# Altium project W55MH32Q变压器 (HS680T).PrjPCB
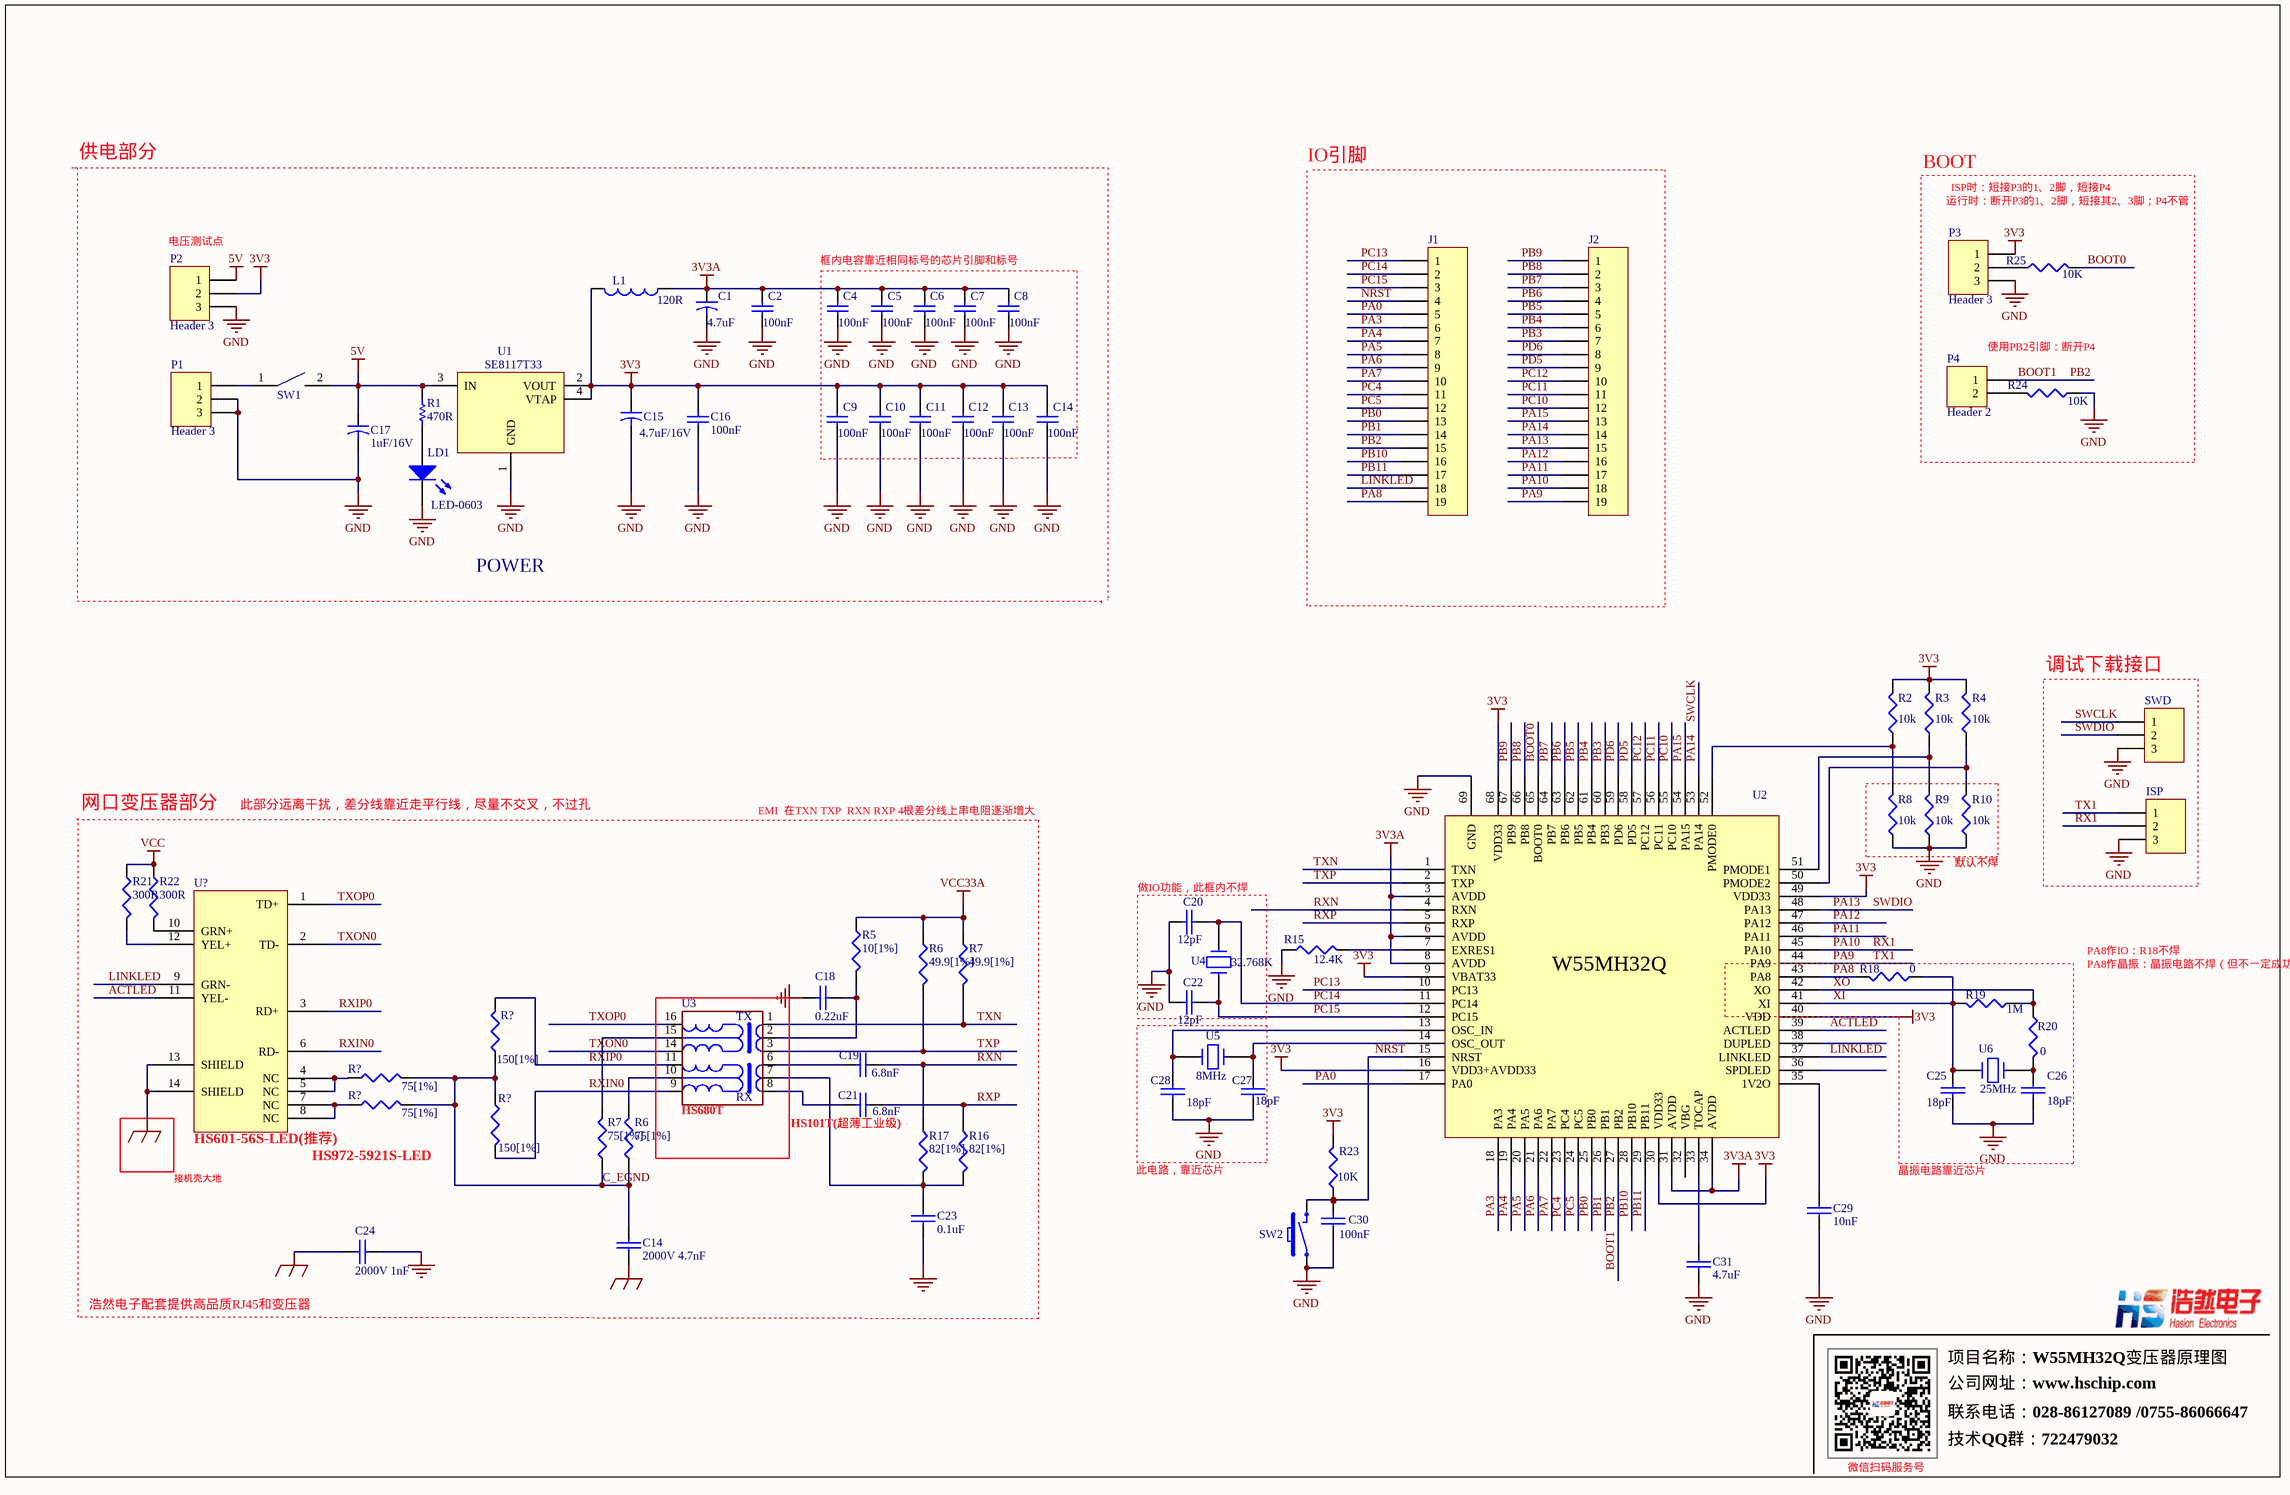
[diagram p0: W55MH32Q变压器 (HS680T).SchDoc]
1 sheet, 77 parts. Net scope: global (net labels, ports and power ports of the same name join across sheets).

## Sheet W55MH32Q变压器 (HS680T).SchDoc
size 431 x 279 mm; PageSetup: Record=PageOptions?CenterHorizontal=True?CenterVertical=True?PrintScale=0.68?XCorrection=1.00?YCorrection=1.00?PrintKind=0?BorderSize=5000000?LeftOffset=0?BottomOffset=0?Orientation=2?PaperLength=1000?PaperWidth=1000?Scale=100?PaperSource=7?PrintQuality=-4?MediaType=1?DitherType=10?PaperKind=A4?PrintScaleMode=1

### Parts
(Parts that share a designator on the sheet are numbered #1, #2 ... from top to bottom, then left to right.)
C1  4.7uF  [3216]
C2  100nF  [0402]
C4  100nF  [0402]
C5  100nF  [0402]
C6  100nF  [0402]
C7  100nF  [0402]
C8  100nF  [0402]
C9  100nF  [0402]
C10  100nF  [0402]
C11  100nF  [0402]
C12  100nF  [0402]
C13  100nF  [0402]
C14#1  100nF  [0402]
C14#2  2000V 4.7nF  [0603]
C15  4.7uF/16V  [3216]
C16  100nF  [0402]
C17  1uF/16V  [3216]
C18  0.22uF  [0603]
C19  6.8nF  [0603]
C20  12pF  [0402]
C21  6.8nF  [0603]
C22  12pF  [0402]
C23  0.1uF  [0603]
C24  2000V 1nF  [0603]
C25  18pF  [0402]
C26  18pF  [0402]
C27  18pF  [0402]
C28  18pF  [0402]
C29  10nF  [0402]
C30  100nF  [0402]
C31  4.7uF  [3216]
ISP  Header 3  [HDR1X3]  (value not drawn)
J1  Header 19  [SIP19]  (value not drawn)
J2  Header 19  [SIP19]  (value not drawn)
L1  120R  [0603]
LD1  LED-0603  [0603 - LED]
P1  Header 3  [PLUG]
P2  Header 3  [HDR1X3]
P3  Header 3  [HDR1X3]
P4  Header 2  [HDR1X2]
R1  470R  [0402]
R2  10k  [0402]
R3  10k  [0402]
R4  10k  [0402]
R5  10[1%]  [0603]
R6#1  49.9[1%]  [0603]
R6#2  75[1%]  [0603]
R7#1  49.9[1%]  [0603]
R7#2  75[1%]  [0603]
R8  10k  [0402]
R9  10k  [0402]
R10  10k  [0402]
R15  12.4K  [0402]
R16  82[1%]  [0603]
R17  82[1%]  [0603]
R18  0  [0402]
R19  1M  [0402]
R20  0  [0402]
R21  300R  [0603]
R22  300R  [0603]
R23  10K  [0402]
R24  10K  [0402]
R25  10K  [0402]
R?#1  150[1%]  [0603]
R?#2  75[1%]  [0603]
R?#3  75[1%]  [0603]
R?#4  150[1%]  [0603]
SW1  SW  [SWITCH-3]  (value not drawn)
SW2  RSTn  [PB-4]  (value not drawn)
SWD  Header 3  [HDR1X3]  (value not drawn)
U1  SE8117T33  [SOT-223]
U2  W55MH32Q  [QFN68-W55MH32Q 8X8-P0.4-EP5.5]  (value not drawn)
U3  HS680T  [TR-HS101T/HS102T/HS680T]
U4  32.768K  [OSC-CH206-RA - 2]
U5  8MHz  [XTAL-49S]
U6  25MHz  [XTAL-49S]
U?  HS601-56S-LED(推荐)  [RJ45-HS601-56S-LED]

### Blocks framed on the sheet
BOOT: P3 P4 R24 R25
框内电容靠近相同标号的芯片引脚和标号: C4-C13 C14#1
调试下载接口: ISP SWD
网口变压器部分: C14#2 C18 C19 C21 C23 C24 R5 R6#1 R6#2 R7#1 R7#2 R16 R17 R21 R22 R?#1-R?#4 U3 U?
做IO功能，此框内不焊: C20 C22 U4

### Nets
3V3: C9.2 C10.2 C11.2 C12.2 C13.2 C14#1.2 C15.1 C16.2 L1.2 P2.2 P3.1 R2.2 R3.2 R4.2 R23.2 U1.2(VOUT) U1.4(VTAP) U2.9(VBAT33) U2.16(VDD3+AVDD33) U2.30(VDD33) U2.40(VDD) U2.49(VDD33) U2.68(VDD33)
3V3A: C1.1 C2.2 C4.2 C5.2 C6.2 C7.2 C8.2 L1.1 U2.3(AVDD) U2.6(AVDD) U2.8(AVDD) U2.31(AVDD) U2.34(AVDD)
5V: C17.1 P2.1 R1.1 SW1.2 U1.3(IN)
EARTH: C14#2.1 C24.1 U?.13(SHIELD) U?.14(SHIELD)
GND: C1.2 C2.1 C4.1 C5.1 C6.1 C7.1 C8.1 C9.1 C10.1 C11.1 C12.1 C13.1 C14#1.1 C15.2 C16.1 C17.2 C18.1 C20.1 C22.1 C23.1 C24.2 C25.2 C26.2 C27.2 C28.2 C29.2 C30.1 C31.2 ISP.3 LD1.2(K) P1.2 P1.3 P2.3 P3.3 R8.1 R9.1 R10.1 R15.1 R24.1 SW2.1 SWD.3 U1.1(GND) U2.69(GND)
VCC: R21.2 R22.2
VCC33A: R5.2 R6#1.2 R7#1.2
ACTLED: U2.39(ACTLED) U?.11(YEL-)
BOOT0: R25.1 U2.65(BOOT0)
BOOT1: J1.15 P4.1 U2.27(PB2)  [also labelled PB2]
C_EGND: C14#2.2 R6#2.2 R7#2.2 R?#1.2 R?#2.1 R?#3.1 R?#4.2
LINKLED: J1.18 U2.37(LINKLED) U?.9(GRN-)
NRST: C30.2 J1.4 R23.1 SW2.2 U2.15(NRST)
PA0: J1.5 U2.17(PA0)
PA3: J1.6 U2.18(PA3)
PA4: J1.7 U2.19(PA4)
PA5: J1.8 U2.20(PA5)
PA6: J1.9 U2.21(PA6)
PA7: J1.10 U2.22(PA7)
PA8: J1.19 R18.2 U2.43(PA8)
PA9: ISP.1 J2.19 U2.44(PA9)  [also labelled TX1]
PA10: ISP.2 J2.18 U2.45(PA10)  [also labelled RX1]
PA11: J2.17 U2.46(PA11)
PA12: J2.16 U2.47(PA12)
PA13: J2.15 SWD.2 U2.48(PA13)  [also labelled SWDIO]
PA14: J2.14 SWD.1 U2.53(PA14)  [also labelled SWCLK]
PA15: J2.13 U2.54(PA15)
PB0: J1.13 U2.25(PB0)
PB1: J1.14 U2.26(PB1)
PB3: J2.7 U2.60(PB3)
PB4: J2.6 U2.61(PB4)
PB5: J2.5 U2.62(PB5)
PB6: J2.4 U2.63(PB6)
PB7: J2.3 U2.64(PB7)
PB8: J2.2 U2.66(PB8)
PB9: J2.1 U2.67(PB9)
PB10: J1.16 U2.28(PB10)
PB11: J1.17 U2.29(PB11)
PC4: J1.11 U2.23(PC4)
PC5: J1.12 U2.24(PC5)
PC10: J2.12 U2.55(PC10)
PC11: J2.11 U2.56(PC11)
PC12: J2.10 U2.57(PC12)
PC13: J1.1 U2.10(PC13)
PC14: C20.2 J1.2 U2.11(PC14) U4.1
PC15: C22.2 J1.3 U2.12(PC15) U4.2
PD5: J2.9 U2.58(PD5)
PD6: J2.8 U2.59(PD6)
RXIN0: R?#4.1 U3.9 U?.6(RD-)
RXIP0: R?#1.1 U3.11 U?.3(RD+)
RXN: C19.1 R17.2 U2.4(RXN)
RXP: C21.1 R16.2 U2.5(RXP)
TXN: R7#1.1 U2.1(TXN) U3.1
TXON0: U3.14 U?.2(TD-)
TXOP0: U3.16 U?.1(TD+)
TXP: R6#1.1 U2.2(TXP) U3.3
XI: C25.1 R18.1 R19.2 U2.41(XI) U6.1
XO: R19.1 R20.1 U2.42(XO)
NetC18_2: C18.2 R5.1 U3.2
NetC19_2: C19.2 U3.6
NetC21_2: C21.2 U3.8
NetC23_2: C23.2 R16.1 R17.1 U3.7
NetC26_1: C26.1 R20.2 U6.2
NetC27_1: C27.1 U2.14(OSC_OUT) U5.1
NetC28_1: C28.1 U2.13(OSC_IN) U5.2
NetC29_1: C29.1 U2.35(1V2O)
NetC31_1: C31.1 U2.33(TOCAP)
NetLD1_1: LD1.1(A) R1.2
NetP1_1: P1.1 SW1.1
NetP3_2: P3.2 R25.2
NetP4_2: P4.2 R24.2
NetR2_1: R2.1 R8.2 U2.52(PMODE0)
NetR3_1: R3.1 R9.2 U2.51(PMODE1)
NetR4_1: R4.1 R10.2 U2.50(PMODE2)
NetR6#2_1: R6#2.1 U3.10
NetR7#2_1: R7#2.1 U3.15
NetR15_2: R15.2 U2.7(EXRES1)
NetR21_1: R21.1 U?.12(YEL+)
NetR22_1: R22.1 U?.10(GRN+)
NetR?#2_2: R?#2.2 U?.4(NC) U?.5(NC)
NetR?#3_2: R?#3.2 U?.7(NC) U?.8(NC)

Not connected (* = marked no-connect by the designer): U2 32(VBG) 36(SPDLED) 38(DUPLED)

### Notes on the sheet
- 供电部分
- IO引脚
- 运行时：断开P3的1、2脚，短接其2、3脚；P4不管
- ISP时：短接P3的1、2脚，短接P4
- (near P2) 电压测试点
- 使用PB2引脚：断开P4
- POWER
- 此部分远离干扰，差分线靠近走平行线，尽量不交叉，不过孔
- EMI  在TXN TXP  RXN RXP 4根差分线上串电阻逐渐增大
- 默认不焊
- PA8作晶振：晶振电路不焊（但不一定成功）
- PA8作IO：R18不焊
- (near U?) HS972-5921S-LED
- (near U3) HS101T(超薄工业级)
- 接机壳大地
- 此电路，靠近芯片
- 晶振电路靠近芯片
- 浩然电子配套提供高品质RJ45和变压器
- 项目名称：W55MH32Q变压器原理图
- 公司网址：www.hschip.com
- 联系电话：028-86127089 /0755-86066647
- 微信扫码服务号
- 技术QQ群：722479032

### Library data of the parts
C1 C15 C17 = CAP-A Size: Tantla CAP A Size EIA/IECQ 3216
C2 C4-C13 C14#1 C16 = CAP-0603: Ceramic CAP 0603(1608)
C14#2 C18-C31 = CAP: Capacitor
ISP P1-P3 SWD = Header 3: Header, 3-Pin
J1 J2 = Header 19: Header, 18-Pin
L1 = IND-0603: Inductor 0603(1608)
P4 = Header 2: Header, 2-Pin
R1 = RES-0603
R2-R4 R8-R10 R18-R20 R23-R25 = Res3: Resistor
R5 R6#1 R6#2 R7#1 R7#2 R15-R17 R21 R22 R?#1-R?#4 = RES1
SW1 = swtch
SW2 = IT-1101NHA-180G: TACT Switch (SMD)
U1 = AME8815BEGT330Z: 1.5A CMOS LDO
U2 = W55MH32_68QFN_EVB
U3 = HS102T
U4-U6 = CRYSTAL
U? = HS601 /HS972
